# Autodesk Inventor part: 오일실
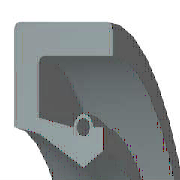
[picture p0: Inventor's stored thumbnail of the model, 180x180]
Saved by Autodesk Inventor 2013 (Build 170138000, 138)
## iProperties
IsCustomPart: 1
Created: 2015-10
Part Number: 오일실
Material: 고무
Description: 오일-실
Document SubType Name: Modeling
Standard: KS B 2804
Designer: mdu
Standards Organization: KS
Language: ko-KR
Size Designation: S - 25 38 8
Categories: <MemberInstance><Categories><Category DisplayName="샤프트 부품" InternalName="7f7aeb1f-a693-4053-b835-cee3144e0d98" Mnemonic="SHFT"><Category DisplayName="실링" Intern
Density: 0.93 g/cm^3
Author: mdu
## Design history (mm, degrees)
revolve "본체" stored, may be unused: angle "d17" = 90 deg
revolve "스프링1" stored, may be unused: angle "d18" = 90 deg
body "Solid1"
sketch "스케치1"
  geometry: L1 (0, 19)-(8, 19); L2 (8, 19)-(8, 17.75); L3 (8, 17.75)-(1.75, 17.75); L4 (0, 19)-(0, 14.6); L5 (0, 14.6)-(1.75, 14.25); L6 (1.75, 14.25)-(4.9, 12.5); L7 (4.9, 12.5)-(0, 12.5); L8 (6.3, 13.375)-(6.3, 14.6); L9 (0, 0)-(9.586, 0) reference; L10 (4.9, 12.5)-(6.3, 13.375); L11 (0, 18)-(0, -3) reference; L12 (-1.917, 0)-(11.503, 0) reference; L13 (4.2, 14.6)-(1.75, 15.09); L14 (1.75, 15.09)-(1.75, 17.75); L15 (6.3, 14.6)-(5.6, 14.6); C1 r 0.455 at (4.9, 14.6); A1 r 0.7 centre (4.9, 14.6) between (5.6, 14.6) and (4.2, 14.6)
  constraints: 26 end point, 5 horizontal alignment, 4 perpendicular, 2 centre point, 2 collinear, 2 horizontal, 2 parallel, 2 point on circle, 2 point on line, 2 vertical alignment, 1 coincident
  dimensions: "d0" = 38 diameter of L1 L9 (= SD2); "d1" = 26.75 diameter of L8.start L9 (= ABDM); "d2" = 1.25 distance of L1.end L2.end (computed from SD); "d3" = 0.91 diameter of C1 (= SPDI); "d4" = 1.4 diameter of A1 (= SPDA); "d5" = 25 diameter of L6.end L9 (= NND); "d6" = 28.5 diameter of L5.end L9 (= TKDM); "d7" = 29.2 diameter of L4.end L9 (= HLDM); "d8" = 4.9 distance from line of C1.centre L4 (= SPDST); "d9" = 6.3 distance between parallel lines of L8 L4 (= SDI); "d10" = 8 distance between parallel lines of L2 L4 (= SWDT); "d12" = 1.75 distance between parallel lines of L14 L4 (= SD)
fillet "모깎기1" dims "d11" = 0.3 (= RR)
other parameters: "SD2" = 38 [user parameter; used in 1 equation term], "SWDT" = 8 [user parameter; used in 1 equation term], "RR" = 0.3 [user parameter; used in 1 equation term], "SD" = 1.75 [user parameter; used in 2 equation terms], "NND" = 25 [user parameter; used in 1 equation term], "SPDA" = 1.4 [user parameter; used in 1 equation term], "SPDI" = 0.91 [user parameter; used in 1 equation term], "TKDM" = 28.5 [user parameter; used in 1 equation term], "HLDM" = 29.2 [user parameter; used in 1 equation term], "ABDM" = 26.75 [user parameter; used in 1 equation term], "SDI" = 6.3 [user parameter; used in 1 equation term], "SPDST" = 4.9 [user parameter; used in 1 equation term], "d13" = 0, "d14" = 0, "d15" = 0, "LAB" = 0.35 [user parameter]
